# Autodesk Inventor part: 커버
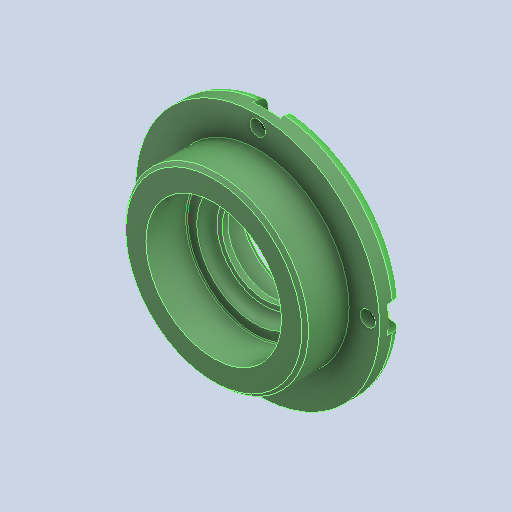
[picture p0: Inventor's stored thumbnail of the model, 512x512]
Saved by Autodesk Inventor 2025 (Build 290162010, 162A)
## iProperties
Created: 2024-07
Part Number: 커버
Material: 강철, 연강
Document SubType Name: Modeling
Designer: Admin
Density: 7.86 g/cm^3
Appearance: 기본값
Company: 한국ATC센터
Author: jhkim
Revision Number: 1
Sending System: Autodesk Inventor 2025
Preprocessor: ST-DEVELOPER v20
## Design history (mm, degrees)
feature "솔리드1"
node "솔리드2"
